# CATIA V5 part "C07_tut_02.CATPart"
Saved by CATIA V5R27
Part number: Part1
Bounding box of the stored display mesh (mm): x 0 to 32, y -32 to 32, z -15 to 36
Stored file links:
  E:\_Deepak\2017_Deepak\CATIA\Resources\Tutorial Files\Tutorials\c07_catia_v5_6r2016_tut\C07_tut_02.CATPart
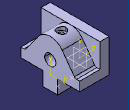
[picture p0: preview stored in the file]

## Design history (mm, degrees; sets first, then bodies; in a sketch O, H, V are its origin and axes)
Body1 (main body)
  Sketch1 on zx-plane, origin (0, 0, 0), H (-1, 0, 0), V (0, 0, 1)
    point P1 (0, 36)
    line L1 (0, 36) -> (0, 0)
    line L2 (0, 0) -> (-32, 0)
    line L3 (0, 36) -> (-10, 36)
    line L4 (-10, 36) -> (-10, 10)
    line L5 (-10, 10) -> (-32, 10)
    line L6 (-32, 10) -> (-32, 0)
    length L2 = 32
    length L3 = 10
    length L6 = 10
    distance L3 L2 = 36
    coincidence: P1 V
    vertical: L1 V, L4 V, L6 V
    horizontal: L2 H, L3 H, L5 H
  Pad1: profile Sketch1, direction (0, 1, 0), length 32, mirrored extent
  Sketch2 on face of Pad1 from Sketch1.L6, origin (32, 0, 0), H (0, 1, 0), V (0, 0, 1)
    arc A1 centre (0, 20) radius 16 from (12.9443, 29.4046) to (-12.9443, 29.4046) ccw
    point P1 (0, 20)
    reference projected line E1 (-32, 36) -> (32, 36) from edge [face of Pad1 from Sketch1.L4 | face of Pad1 from Sketch1.L3]
    line L1 (-27.0425, 10) -> (27.0425, 10)
    point P2 (-27.0425, 10)
    point P3 (27.0425, 10)
    reference projected line E2 (-32, 10) -> (32, 10) from edge [face of Pad1 from Sketch1.L6 | face of Pad1 from Sketch1.L5]
    line L2 (-27.0425, 10) -> (-12.9443, 29.4046)
    line L3 (27.0425, 10) -> (12.9443, 29.4046)
    radius A1 = 16
    angle L3 L2 = 72
    coincidence: P1 V, L1 E2
    tangency: A1 E1, L2 A1, L3 A1
    horizontal: L1 H
    symmetry: P3 P2 V
  Pad2: profile Sketch2, direction (1, 0, 0), up to the existing solid (limit type 2)
  Sketch3 on face of Pad2, origin (32, 0, 0), H (0, 1, 0), V (0, 0, 1)
    line L1 (-8, 0) -> (8, 0)
    line L2 (8, 0) -> (8, -15)
    line L3 (8, -15) -> (-8, -15)
    line L4 (-8, -15) -> (-8, 0)
    reference projected line E1 (-32, 0) -> (32, 0) from edge [face of Pad1 from Sketch1.L2 | face of Pad1 from Sketch1.L6]
    length L2 = 15
    length L3 = 16
    horizontal: L1 H, L3 H
    vertical: L2 V, L4 V
    symmetry: L2 L4 V
    coincidence: L1 E1
  Pad3: profile Sketch3, direction (1, 0, 0), up to face of Pad1 from Sketch1.L1
  Sketch4 on zx-plane, origin (0, 0, 0), H (-1, 0, 0), V (0, 0, 1)
    point P1 (-20, 36)
    reference projected line E1 (0, 36) -> (-10, 36) from edge [face of Pad1 from Sketch1.L3 | end face of Pad1]
    reference projected line E2 (0, 0) -> (0, 36) from edge [face of Pad1 from Sketch1.L1 | end face of Pad1]
    distance P1 E2 = 20
    coincidence: P1 E1
  Sketch5 on {plane type Tangent, Support face of Pad2 from Sketch2.A1, RefPoint Sketch4.P1}, origin (20, 0, 36), H (1, 0, 0), V (0, -1, 0)
    point P1 (0, 0)
    reference projected point E1 (0, 0) from Sketch4.P1
    coincidence: E1 P1
  Hole1: placed by Sketch5, at (20, 0, 36) direction (0, 0, -1), diameter 6, depth 16, V-bottom angle 120, counterbore diameter 10, counterbore depth 4
  Sketch6 on face of Pad2, origin (32, 0, 0), H (0, 1, 0), V (0, 0, 1)
    point P1 (0, 14)
    reference projected line E1 (-8, -15) -> (8, -15) from edge [face of Pad3 from Sketch3.L3 | start face of Pad3]
    distance P1 E1 = 29
    coincidence: P1 V
  Sketch7 on face of Pad2, origin (32, 0, 10), H (0, 1, 0), V (0, 0, 1)
    point P1 (0, 4)
    reference projected point E1 (0, 4) from Sketch6.P1
    coincidence: E1 P1
  Hole2: placed by Sketch7, at (32, 0, 14) direction (-1, 0, 0), diameter 12, depth 24
  Fillet1: radius 3, on edge [face of Pad1 from Sketch1.L5 | face of Pad2 from Sketch2.L3]; edge [face of Pad2 from Sketch2.L2 | face of Pad1 from Sketch1.L5]
  Sketch8 on zx-plane, origin (0, 0, 0), H (-1, 0, 0), V (0, 0, 1)
    point P1 (-24, -15)
    point P2 (-8, -15)
    reference projected line E1 (-32, -15) -> (0, -15) from edge [face of Pad3 from Sketch3.L3 | face of Pad3 from Sketch3.L2]
    reference projected line E2 (-32, -15) -> (0, -15) from edge [face of Pad3 from Sketch3.L3 | face of Pad3 from Sketch3.L2]
    reference projected line E3 (-32, -15) -> (-32, 0) from edge [face of Pad3 from Sketch3.L2 | face of Pad2]
    distance E3 P1 = 8
    distance P2 P1 = 16
    coincidence: P1 E1, P2 E2
  Sketch9 on face of Pad3 from Sketch3.L3, origin (8, 0, -15), H (1, 0, 0), V (0, -1, 0)
    point P1 (0, 0)
    reference projected point E1 (0, 0) from Sketch8.P2
    coincidence: E1 P1
  Hole3: placed by Sketch9, at (8, 0, -15) direction (0, 0, 1), diameter 6, depth 16, V-bottom angle 120
  Sketch10 on face of Pad3 from Sketch3.L3, origin (24, 0, -15), H (1, 0, 0), V (0, -1, 0)
    point P1 (0, 0)
    reference projected point E1 (0, 0) from Sketch8.P1
    coincidence: E1 P1
  Hole4: placed by Sketch10, at (24, 0, -15) direction (0, 0, 1), diameter 6, depth 16, V-bottom angle 120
